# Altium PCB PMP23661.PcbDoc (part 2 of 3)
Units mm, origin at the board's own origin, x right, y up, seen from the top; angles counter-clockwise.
Board outline 209 x 127 mm, 4 copper layers (Top Layer, Layer 1, Layer 2, Bottom Layer), stack 1.787 mm thick; 235 components, 114 nets, 814 pads, 405 vias.
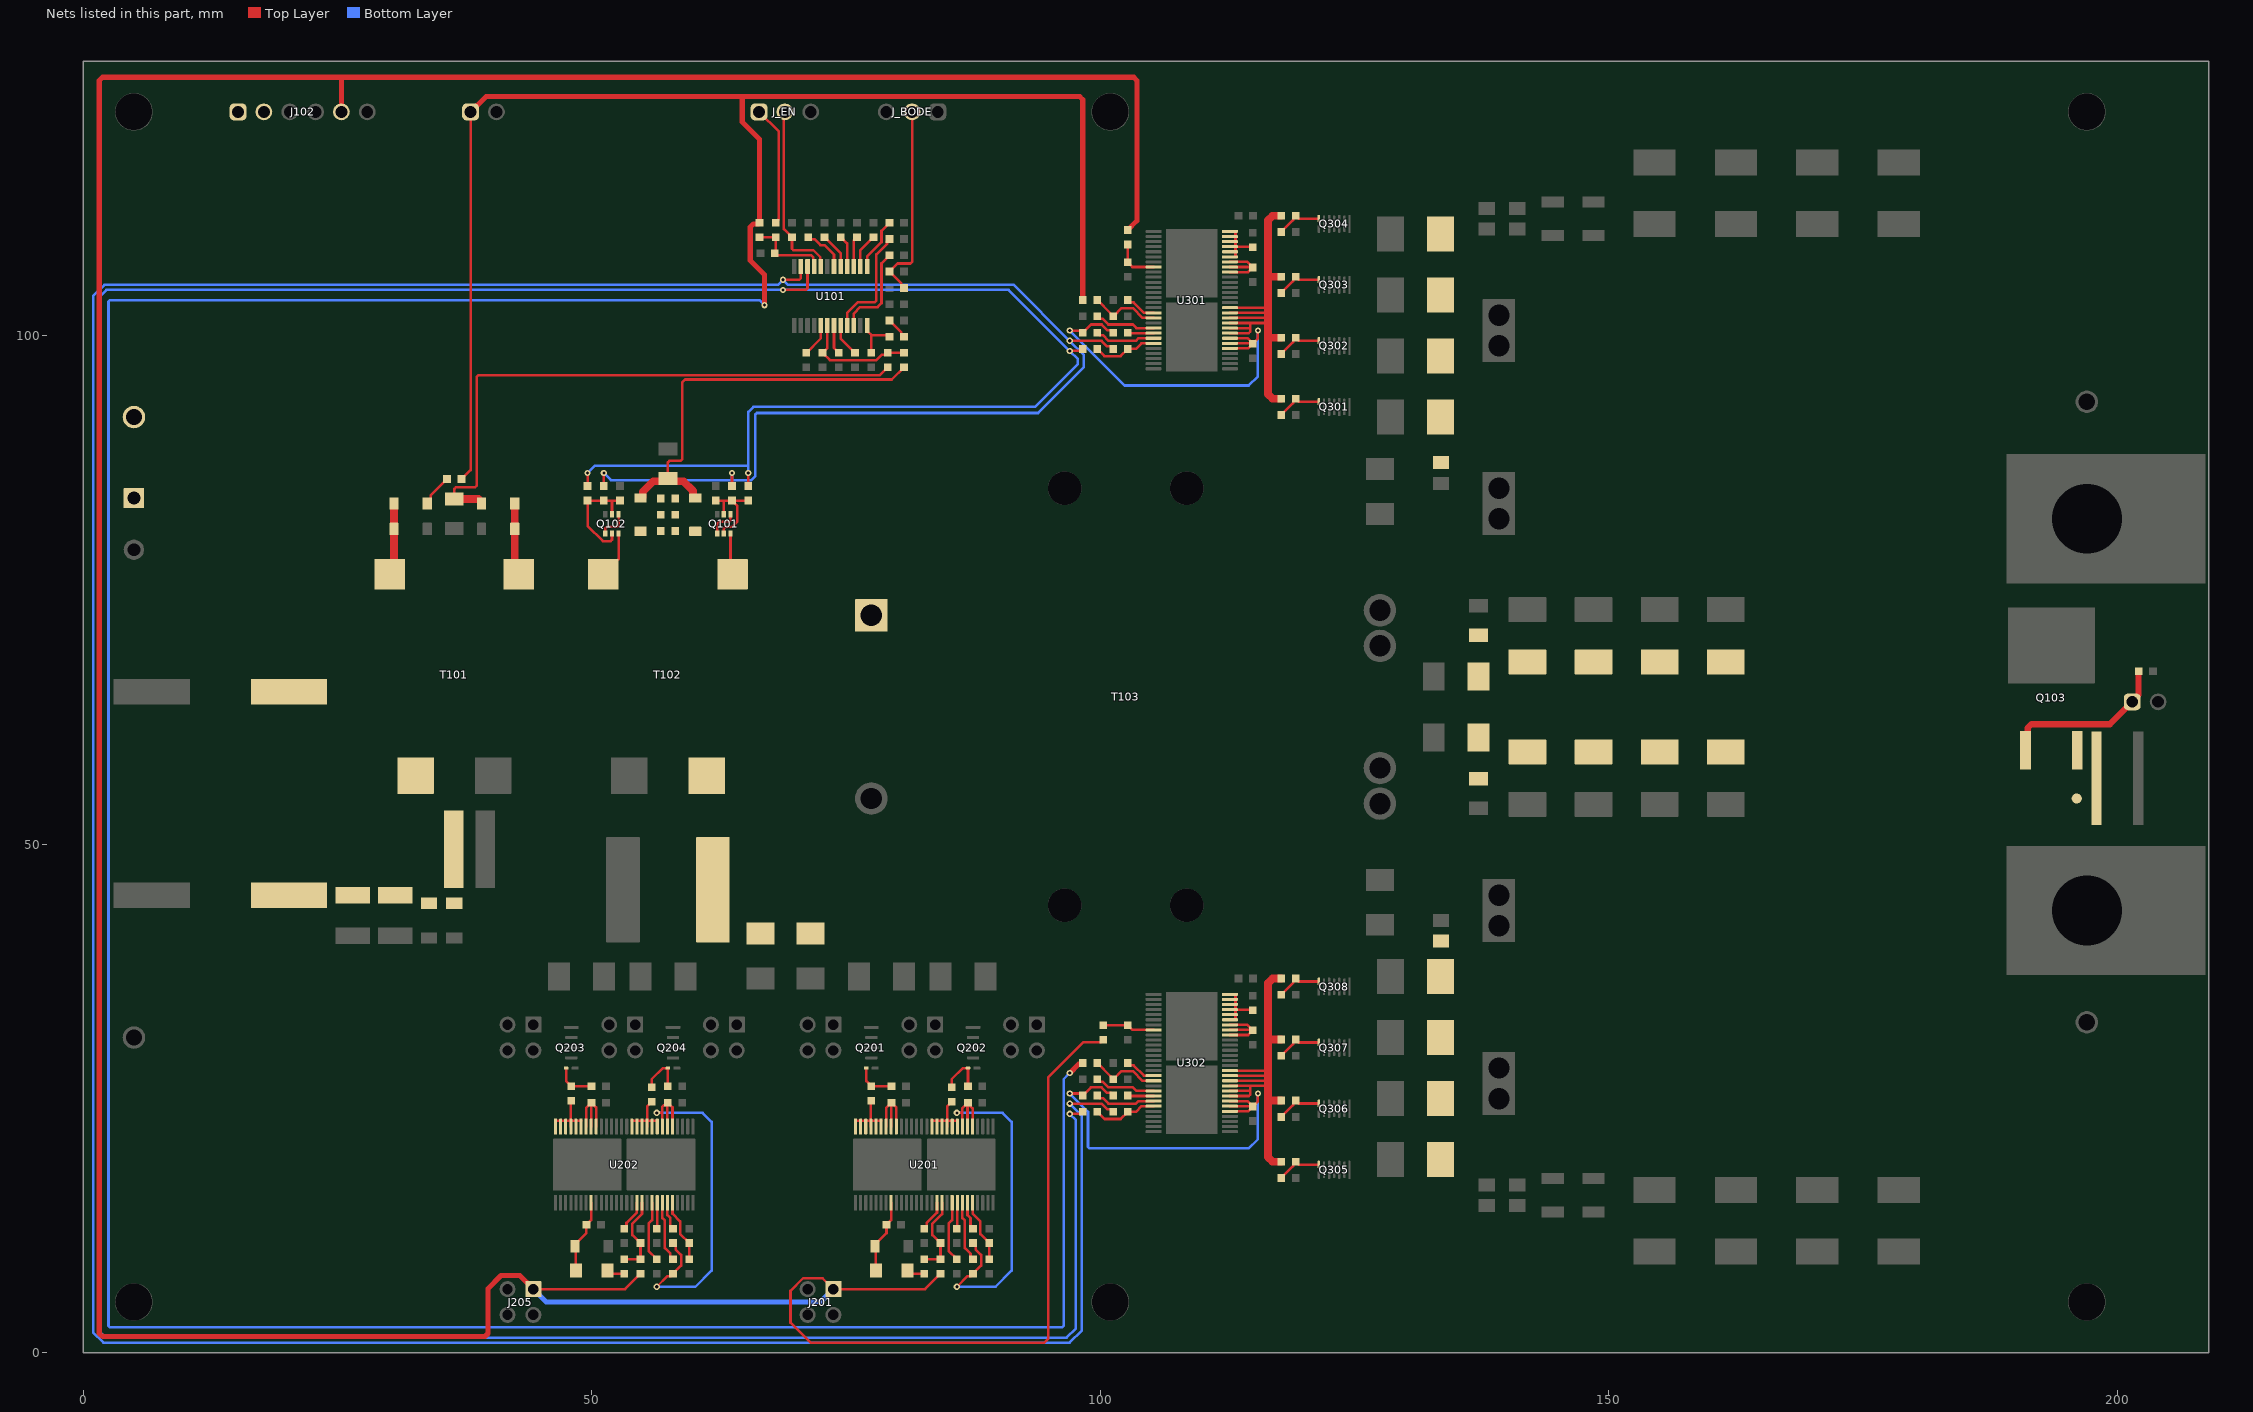
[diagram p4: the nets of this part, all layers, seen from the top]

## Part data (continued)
C109: library part CMP-0007425-5, "CAP, CERM, 5600 pF, 25 V, +/- 10%, X7R, 0603", Cap_Case=0603, Manufacturer=MuRata, Supplier Part Number 1=GRM188R71E562KA01D-ND, TempCo=X7R, Tolerance_%=10%, Value1=Unknown, Value2=25V, ValueDisplayed=5600pF
C110: library part CMP-0084679-1, "CAP, CERM, 0.1 µF, 25 V,+/- 10%, X7R, AEC-Q200 Grade 1, 0603", Cap_Case=0603, Manufacturer=MuRata, TempCo=X7R, Tolerance_%=10%, Value2=25V, ValueDisplayed=0.1µF
C111: library part CMP-0007138-4, "CAP, CERM, 0.47 uF, 16 V, +/- 10%, X7R, AEC-Q200 Grade 1, 0603", Cap_Case=0603, Manufacturer=MuRata, Supplier Part Number 1=490-4775-1-ND, TempCo=X7R, Tolerance_%=10%, Value1=Unknown, Value2=16V, ValueDisplayed=0.47uF
C112: library part CMP-0084283-1, "CAP, CERM, 10 pF, 100 V,+/- 5%, C0G/NP0, AEC-Q200 Grade 1, 0603", Cap_Case=0603, Manufacturer=MuRata, TempCo=C0G/NP0, Tolerance_%=5%, Value2=100V, ValueDisplayed=10pF
C113: library part CMP-0007407-5, "CAP, CERM, 0.012 uF, 25 V, +/- 10%, X7R, 0603", Cap_Case=0603, Manufacturer=MuRata, Supplier Part Number 1=GRM188R71E123KA01D-ND, TempCo=X7R, Tolerance_%=10%, Value1=Unknown, Value2=25V, ValueDisplayed=0.012uF
C114: library part CMP-0007455-4, "CAP, CERM, 470 pF, 50 V, +/- 10%, X7R, 0603", Cap_Case=0603, Manufacturer=MuRata, Supplier Part Number 1=490-1489-1-ND, TempCo=X7R, Tolerance_%=10%, Value1=Unknown, Value2=50V, ValueDisplayed=470pF
C115 C119 C123 C127: library part CMP-0007728-2, "CAP, CERM, 1 uF, 25 V, +/- 10%, X7R, 0805", Cap_Case=0805, Manufacturer=Kemet, Supplier Part Number 1=399-8004-1-ND, TempCo=X7R, Tolerance_%=10%, Value1=Unknown, Value2=25V, ValueDisplayed=1uF
C116 C120 C124 C128: library part CMP-0009078-1, "CAP, CERM, 10 uF, 25 V, +/- 10%, X7R, 1210", Cap_Case=1210, Manufacturer=Kemet, Supplier Part Number 1=399-8224-1-ND, TempCo=X7R, Tolerance_%=10%, Value1=Unknown, Value2=25V, ValueDisplayed=10uF
C117 C118 C121 C122 C125 C126 C129 C130: library part CMP-0012025-2, "CAP, TA, 100 uF, 25 V, +/- 10%, 0.1 ohm, SMD", Cap_Case=E, Manufacturer=Kemet, Supplier Part Number 1=399-5221-1-ND, Tolerance_%=10%, Value1="0.1 ohm", Value2=25V, ValueDisplayed=100uF
C201 C207: library part CMP-0007171-4, "CAP, CERM, 100 pF, 50 V, +/- 5%, C0G/NP0, 0603", Cap_Case=0603, Manufacturer=MuRata, Supplier Part Number 1=490-1427-1-ND, TempCo=C0G/NP0, Tolerance_%=5%, Value1=Unknown, Value2=50V, ValueDisplayed=100pF
C204 C210 C303 C310: library part CMP-0079602-1, "CAP, CERM, 0.1 µF, 50 V,+/- 10%, X7R, AEC-Q200 Grade 1, 0603", Cap_Case=0603, Manufacturer=Kemet, Supplier Part Number 1=399-6856-1-ND, TempCo=X7R, Tolerance_%=10%, Value2=50V, ValueDisplayed=0.1µF
C305 C312: library part CMP-0008881-2, "CAP, CERM, 0.1 uF, 100 V, +/- 10%, X7R, 1206", Cap_Case=1206, Manufacturer=MuRata, Supplier Part Number 1=490-3364-1-ND, TempCo=X7R, Tolerance_%=10%, Value1=Unknown, Value2=100V, ValueDisplayed=0.1uF
C307 C314: library part CMP-0008098-2, "CAP, CERM, 1200 pF, 100 V, +/- 5%, C0G/NP0, 0805", Cap_Case=0805, Manufacturer=MuRata, Supplier Part Number 1=GRM2165C2A122JA01D-ND, TempCo=C0G/NP0, Tolerance_%=5%, Value1=Unknown, Value2=100V, ValueDisplayed=1200pF
D101 D102 D103 D104 D109 D112: library part CMP-0090343-1, "Diode Schottky 100V 250mA (DC) Surface Mount SOD-123", Digikey Part Number=1727-7326-1-ND, Forward Current=250mA, Manufacturer=Nexperia, Max Surge Forward Current=2.5A, Mouser Part Number=841-BAT46GWJ, Operating Temperature Range="to +150°C", Peak Reverse Current=2uA, ValueDisplayed=39pF
D105 D106 D107 D108 D110 D111: library part CMP-0028599-2, "Diode, Schottky, 200 V, 3 A, SMB", Manufacturer="ON Semiconductor", Value1=3A, Value2=0.84V
D113 D114 D301 D302: library part CMP-0028521-2, "Diode, Schottky, 100 V, 1 A, SMB", Manufacturer="ON Semiconductor", Value1=1A, Value2=0.75V
D201 D203: library part CMP-0095320-1, "Diode Schottky 200 V 1A Surface Mount SOD-123W", Digikey Part Number=SS1H20LWRVGCT-ND, Forward Current=1A, Manufacturer="Taiwan Semiconductor", Max Surge Forward Current=30A, Mouser Part Number=821-SS1H20LW, Operating Temperature Range="-55°C to +175°C", Peak Reverse Current=0.1mA
D202 D204: library part CMP-0005752-4, "Diode, Zener, 13 V, 500 mW, SOD-123", Manufacturer="Diodes Inc.", Power_W=500mW, Value1=0.5W
H301 H302 H303 H304 H305 H306: library part CMP-0003652-1, Manufacturer=Keystone, Supplier Part Number 1=36-4820-ND
J101: library part CMP-0074910-1, "Terminal Block, 5.08 mm, 2x1, Brass, TH", Color=Blue, Current_A=15A, Manufacturer="On-Shore Technology", Supplier Part Number 1=ED1609-ND, Voltage_V=300V
J102: library part CMP-0054801-2, "Header, 2.54 mm, 6x1, Gold, TH", Color=Black, Manufacturer="Wurth Elektronik", Supplier Part Number 1=732-5319-ND
J103 J106: library part CMP-0054794-2, "Header, 2.54 mm, 2x1, Gold, TH", Color=Black, Manufacturer="Wurth Elektronik", Supplier Part Number 1=732-5315-ND
J104 J105: library part CMP-0075010-2, "Terminal 70A Lug", Manufacturer=Panduit, Supplier Part Number 1=CXS70-14-C-ND
J201 J202 J203 J204 J205 J206 J207 J208: library part CMP-0127928-1, "Conn Socket Strip SKT 4 POS 2.54mm Solder ST Top Entry Thru-Hole Bulk", Current_A=6.3A, Digikey Part Number=SAM1185-02-ND, Manufacturer=Samtec, Mouser Part Number=200-SSQ10202GD, Operating Temperature Range="-55°C to +125°C", Voltage_V=655V
J_BODE J_EN: library part CMP-0054796-4, "Header, 2.54 mm, 3x1, Gold, TH", Manufacturer="Wurth Elektronik", Supplier Part Number 1=732-5316-ND
L101: library part CMP-0125020-1, "Air Core Inductor, High Current, 117 nH, 44 A, 1212VS Series, ± 20%, 0.00143 ohm, 399 MHz", Manufacturer=Coilcraft, Mouser Part Number=994-1212VS-111MED, Operating Temperature Range=to, Self Resonant Frequency=399MHz, Test Frequency=1MHz, Tolerance_%=20%
L102 L103: library part CMP-0127672-1, "2uH & 48.7Ap INDUCTOR", Manufacturer="Payton Planar", Operating Temperature Range=to
LOGO201: library part CMP-0074835-1, "IEC 61010-1 High Voltage Warning"
Logo301: library part CMP-0074837-2, "IEC 61010-1 Hot Surface Warning", Manufacturer="Texas Instruments"
Logo302: library part CMP-0074836-1, "IEC 61010-1 Caution Warning"
Q101 Q102: library part CMP-0000770-1, "MOSFET, 2-CH, N-CH, 60 V, 0.115 A, SOT-363", Alternate Manufacturer=None, Manufacturer="Fairchild Semiconductor", Supplier Part Number 1=2N7002DWCT-ND
Q103: library part CMP-0097579-1, "MOSFET N-Channel 40 V 194A (Ta) 188W (Ta) Surface Mount DDPAK/TO-263-3", Digikey Part Number=296-51015-1-ND, Drain To Source Breakdown Voltage=40V, Input Capacitace At Vds="4570pF @ 20V", Manufacturer="Texas Instruments", Max Forward Diode Voltage=1V, Mouser Part Number=595-CSD18511KTT, Operating Temperature Range="-55°C to +175°C", Power_W=188W, Pulse Drain Current=400A, Typ Forward Diode Voltage=0.9V
Q201 Q202 Q203 Q204: library part CMP-0033803-1, "MOSFET N-Channel 200 V 32A (Ta) Surface Mount Die", Digikey Part Number=917-1218-1-ND, Drain To Source Breakdown Voltage=200V, Input Capacitace At Vds="1356pF @ 100V", Manufacturer=EPC, Operating Temperature Range="-40°C to +150°C", Pulse Drain Current=162A, Typ Forward Diode Voltage=1.6V
Q301 Q302 Q303 Q304 Q305 Q306 Q307 Q308: library part CMP-0122030-1, "N-Channel 100 V 60A (Ta) Surface Mount Die", Digikey Part Number=917-EPC2088CT-ND, Drain To Source Breakdown Voltage=100V, Input Capacitace At Vds="1864pF @ 50V", Manufacturer=EPC, Operating Temperature Range="-40°C to +150°C", Pulse Drain Current=231A, Typ Forward Diode Voltage=1.5V
R101 R105 R109 R110 R118 R119 R124 R202 R203 R213 R214 R301 R304 R305 R306 R310 R326 R329 R330 R331 R335: library part CMP-0025697-4, "RES, 0, 5%, 0.1 W, AEC-Q200 Grade 0, 0603", Manufacturer=Vishay-Dale, Power_W=100mW, Supplier Part Number 1=541-0.0GCT-ND, TempCo="200 ppm/C", Tolerance_%=5%, Value2=0.1W, Value_Code=0000, ValueDisplayed=0
R102 R103 R107 R114 R115 R116 R205 R206 R216 R217 R303 R328: library part CMP-0022447-4, "RES, 49.9 k, 1%, 0.1 W, AEC-Q200 Grade 0, 0603", Manufacturer=Vishay-Dale, Power_W=100mW, Supplier Part Number 1=541-49.9KHCT-ND, TempCo="100 ppm/C", Tolerance_%=1%, Value2=0.1W, Value_Code=49k9, ValueDisplayed=49.9k
R104 R122: library part CMP-0016768-3, "RES, 1.69, 1%, 0.25 W, AEC-Q200 Grade 0, 1206", Manufacturer=Vishay-Dale, Power_W=250mW, Supplier Part Number 1=541-1.69FFCT-ND, TempCo="100 ppm/C", Tolerance_%=1%, Value2=0.25W, Value_Code=1R69, ValueDisplayed=1.69
R106: library part CMP-0015368-2, "RES, 0, 5%, 2 W, 2512 WIDE", Manufacturer="Vishay Draloric", Power_W=2W, Supplier Part Number 1=RCL0.0ECT-ND, TempCo=ppm/C, Tolerance_%=5%, Value_Code=0000, ValueDisplayed=0
R108: library part CMP-0022052-4, "RES, 147 k, 1%, 0.1 W, AEC-Q200 Grade 0, 0603", Manufacturer=Vishay-Dale, Power_W=100mW, Supplier Part Number 1=541-147KHCT-ND, TempCo="100 ppm/C", Tolerance_%=1%, Value2=0.1W, Value_Code=147k
R111: library part CMP-0022344-4, "RES, 348 k, 1%, 0.1 W, AEC-Q200 Grade 0, 0603", Manufacturer=Vishay-Dale, Power_W=100mW, Supplier Part Number 1=541-348KHCT-ND, TempCo="100 ppm/C", Tolerance_%=1%, Value2=0.1W, Value_Code=348k
R112 R120 R126 R131 R204 R210 R211 R215 R221 R222 R302 R313 R320 R321 R322 R323 R327 R338 R345 R346 R347 R348: library part CMP-0021998-4, "RES, 10.0 k, 1%, 0.1 W, AEC-Q200 Grade 0, 0603", Manufacturer=Vishay-Dale, Power_W=100mW, Supplier Part Number 1=541-10.0KHCT-ND, TempCo="100 ppm/C", Tolerance_%=1%, Value2=0.1W, Value_Code=10k0, ValueDisplayed=10.0k
R113: library part CMP-0022589-4, "RES, 75.0 k, 1%, 0.1 W, AEC-Q200 Grade 0, 0603", Manufacturer=Vishay-Dale, Power_W=100mW, Supplier Part Number 1=541-75.0KHCT-ND, TempCo="100 ppm/C", Tolerance_%=1%, Value2=0.1W, Value_Code=75k0, ValueDisplayed=75.0k
R117: library part CMP-0025736-4, "RES, 1.0 M, 5%, 0.1 W, AEC-Q200 Grade 0, 0603", Manufacturer=Vishay-Dale, Power_W=100mW, Supplier Part Number 1=541-1.0MGCT-ND, TempCo="200 ppm/C", Tolerance_%=5%, Value2=0.1W, Value_Code=1M00, ValueDisplayed=1.0M
R121: library part CMP-0022552-4, "RES, 68.1 k, 1%, 0.1 W, AEC-Q200 Grade 0, 0603", Manufacturer=Vishay-Dale, Power_W=100mW, Supplier Part Number 1=541-68.1KHCT-ND, TempCo="100 ppm/C", Tolerance_%=1%, Value2=0.1W, Value_Code=68k1, ValueDisplayed=68.1k
R123 R125: library part CMP-0022126-4, "RES, 1.50 k, 1%, 0.1 W, AEC-Q200 Grade 0, 0603", Manufacturer=Vishay-Dale, Power_W=100mW, Supplier Part Number 1=541-1.50KHCT-ND, TempCo="100 ppm/C", Tolerance_%=1%, Value2=0.1W, Value_Code=1k50, ValueDisplayed=1.50k
R127: library part CMP-0022003-4, "RES, 10.0, 1%, 0.1 W, AEC-Q200 Grade 0, 0603", Manufacturer=Vishay-Dale, Power_W=100mW, Supplier Part Number 1=541-10.0HCT-ND, TempCo="100 ppm/C", Tolerance_%=1%, Value2=0.1W, Value_Code=10R0, ValueDisplayed=10.0
R128: library part CMP-0022205-4, "RES, 20.5 k, 1%, 0.1 W, AEC-Q200 Grade 0, 0603", Manufacturer=Vishay-Dale, Power_W=100mW, Supplier Part Number 1=541-20.5KHCT-ND, TempCo="100 ppm/C", Tolerance_%=1%, Value2=0.1W, Value_Code=20k5, ValueDisplayed=20.5k
R129: library part CMP-0022113-4, "RES, 1.10 k, 1%, 0.1 W, AEC-Q200 Grade 0, 0603", Manufacturer=Vishay-Dale, Power_W=100mW, Supplier Part Number 1=541-1.10KHCT-ND, TempCo="100 ppm/C", Tolerance_%=1%, Value2=0.1W, Value_Code=1k10, ValueDisplayed=1.10k
R130: library part CMP-0015082-2, "RES, 0.05, 1%, 4 W, 3518 WIDE", Manufacturer=Ohmite, Power_W=4W, Supplier Part Number 1=FCSL90R050FERCT-ND, TempCo="50 ppm/C", Tolerance_%=1%, Value_Code=R050, ValueDisplayed=0.05
R201 R212: library part CMP-0025700-4, "RES, 100, 5%, 0.1 W, AEC-Q200 Grade 0, 0603", Manufacturer=Vishay-Dale, Power_W=100mW, Supplier Part Number 1=541-100GCT-ND, TempCo="200 ppm/C", Tolerance_%=5%, Value2=0.1W, Value_Code=100R, ValueDisplayed=100
R207 R218: library part CMP-0022732-2, "RES, 2.00, 1%, 0.125 W, 0603", Manufacturer=Vishay/Beyschlag, Power_W=125mW, Supplier Part Number 1=MCT06030C2008FP500-ND, TempCo="50 ppm/C", Tolerance_%=1%, Value2=0.125W, Value_Code=2R00, ValueDisplayed=2.00
R208 R209 R219 R220 R312 R315 R316 R317 R318 R337 R340 R341 R342 R343: library part CMP-0022311-4, "RES, 2.49, 1%, 0.1 W, AEC-Q200 Grade 0, 0603", Manufacturer=Vishay-Dale, Power_W=100mW, Supplier Part Number 1=541-2.49HHCT-ND, TempCo="100 ppm/C", Tolerance_%=1%, Value2=0.1W, Value_Code=2R49, ValueDisplayed=2.49
R307 R308 R309 R311 R332 R333 R334 R336: library part CMP-0122385-1, "10 kOhms ±1% 2W Chip Resistor 2512 (6432 Metric) Current Sense Thick Film", Digikey Part Number=118-CRM2512-FX-1002ELFCT-ND, Manufacturer=Bourns, Mouser Part Number=652-CRM2512FX1002ELF, Operating Temperature Range="-55°C to +155°C", Power_W=2W, TempCo=100ppm/°C, Tolerance_%=1%
R314 R319 R324 R325 R339 R344 R349 R350: library part CMP-0096995-1, "Res Thick Film 2512 33 Ohm 1% 3W ±100ppm/C Pad SMD Automotive T/R", Digikey Part Number=A121219CT-ND, Manufacturer="TE Connectivity", Mouser Part Number=279-3522330KFT, Operating Temperature Range="-55°C to +155°C", Power_W=3W, TempCo=100ppm/°C, Tolerance_%=1%
T101 T102: library part CMP-0122471-1, "Current Transformer 1:50", Manufacturer="Payton Planar", Operating Temperature Range=to
T103: library part CMP-0127699-1, "TITLE 1000W SMPS TRANSFORMER", Manufacturer="Payton Planar", Operating Temperature Range=to
TP101 TP104: library part CMP-0055147-2, "Test Point, Multipurpose, Red, TH", Color=Red, Manufacturer="Keystone Electronics", Supplier Part Number 1=36-5010-ND
TP102 TP105: library part CMP-0055148-2, "Test Point, Multipurpose, Black, TH", Color=Black, Manufacturer="Keystone Electronics", Supplier Part Number 1=36-5011-ND
TP103: library part CMP-0003825-1, "1mm Test Point, SMT", Manufacturer=Any
U101: library part CMP-0092938-1, Manufacturer="Texas Instruments", Operating Temperature Range=to
U201 U202 U301 U302: library part CMP-0120202-4, Manufacturer="Texas Instruments", Operating Temperature Range=to

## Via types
v1: diameter 0.61, hole 0.305, Top Layer to Bottom Layer, 289 vias
v2: diameter 0.813, hole 0.406, Top Layer to Bottom Layer, 116 vias

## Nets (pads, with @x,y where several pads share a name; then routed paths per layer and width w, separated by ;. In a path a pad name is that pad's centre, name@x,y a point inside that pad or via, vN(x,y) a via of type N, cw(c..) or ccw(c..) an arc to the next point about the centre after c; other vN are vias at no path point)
+12Vp: J102.5 J201.1 J205.1 R202.1 R213.1 R310.1 R335.1 | length 421.5
  Top Layer w0.254: J205.1@44.27,6.27 53.281,6.27 R213.1@54.8,7.789 ; R202.1@84.3,7.789 82.781,6.27 ; R335.1@100.3,30.789 100.057,30.546 98.346,30.546 94.9,27.1 94.9,1.4 94.5,1 71.525,1 69.554,2.972 69.554,6.099 70.789,7.334 72.706,7.334 J201.1@73.77,6.27 ; J201.1@73.77,6.27 82.781,6.27 ; J201.1@73.77,6.27 82.781,6.27
  Top Layer w0.508: J102.5@25.4,122 25.4,125.4 ; J205.1@44.27,6.27 42.94,7.6 41.1,7.6 39.8,6.3 39.8,1.898 39.502,1.6 1.898,1.6 1.6,1.898 1.6,125.102 1.898,125.4 25.4,125.4 ; R310.1@102.7,110.394 103.6,111.294 103.6,125.102 103.302,125.4 25.4,125.4
  Bottom Layer w0.508: J205.1@44.27,6.27 45.54,5 72.5,5 J201.1@73.77,6.27
+12Vs: J103.1 R101.2 R105.1 R306.1 R331.1 | length 425.8
  Top Layer w0.254: R105.1@37.211,85.9 38.1,86.789 J103.1@38.1,122
  Top Layer w0.508: J103.1@38.1,122 39.6,123.5 64.8,123.5 ; v1(67,103) 67,106 65.6,107.4 65.6,110.687 65.898,110.984 66.373,110.984 R101.2@66.5,111.111 66.5,119.307 64.8,121.007 64.8,123.5 ; v1@97.019,27.519 97.873,28.373 98.162,28.373 R331.1@98.289,28.5 ; R306.1@98.289,103.5 98.289,123.202 97.991,123.5 64.8,123.5
  Bottom Layer w0.254: v1(67,103) 66.5,103.5 2.649,103.5 2.5,103.351 2.5,2.649 2.649,2.5 96.251,2.5 96.4,2.649 96.4,26.9 v1(97,27.5)
HV: C101.1 C102.1 C103.1 C105.1 C107.1 C108.1 J101.1 J102.1 J102.2 R106.2 T101.1 TP101.1
NetC104_1: C104.1 R101.1 R102.1 U101.9 | length 8.2
  Top Layer w0.254: R101.1@66.5,109.689 R102.1@68.1,109.689 C104.1@68.1,108.3 ; C104.1@68.211,108.3 C104.1@68.011,108.1 68.211,107.9 71.6,107.9 71.799,107.701 71.799,106.876 U101.9@71.875,106.8
NetC106_2: C106.2 U101.17 | length 3.3
  Top Layer w0.254: C106.2@71.1,98.311 72.525,99.736 U101.17@72.525,101
NetC109_2: C109.2 U101.5 | length 3.5
  Top Layer w0.254: C109.2@72.9,109.689 74.475,108.114 U101.5@74.475,106.8
NetC110_1: C110.1 U101.22 | length 9.4
  Top Layer w0.254: U101.22@75.775,101 75.775,102.175 76.4,102.8 78.1,102.8 78.5,103.2 78.5,107.111 C110.1@79.289,107.9
NetC111_2: C111.2 U101.20 | length 3.3
  Top Layer w0.254: U101.20@74.475,101 74.475,99.736 C111.2@75.9,98.311
NetC112_1: C112.1 R123.1 R125.1 U101.18 | length 11.5
  Top Layer w0.254: U101.18@73.175,101 73.175,98.786 C112.1@72.7,98.311 73.411,97.6 78,97.6 78.509,98.109 78.898,98.109 R123.1@79.1,98.311 R125.1@80.7,98.311
NetC113_1: C113.1 R126.1 | length 2.2
  Top Layer w0.254: C113.1@79.289,101.5 80.457,100.332 80.457,100.154 R126.1@80.711,99.9
NetC114_1: C114.1 R126.2 U101.24 | length 4.7
  Top Layer w0.254: U101.24@77.075,101 77.075,100.475 77.5,100.05 ; C114.1@77.5,98.311 77.5,100.05 ; R126.2@79.289,99.9 79.139,100.05 77.5,100.05
NetC201_1: C201.1 R201.1 U201.24 | length 12.4
  Top Layer w0.254: 87.45,13.69 88.208,12.932 ; 87.45,13.69 U201.24@87.45,14.75 87.45,13.69 ; 87.45,13.69 88.208,12.932 ; 88.208,11.681 88.208,12.932 ; 88.208,11.681 C201.1@89.1,10.789 ; 88.208,11.681 C201.1@89.1,10.789 ; 88.208,11.681 88.208,12.932 ; C201.1@89.1,10.789 R201.1@89.1,9.211 C201.1@89.1,10.789
NetC202_1: C202.1 R202.2 R207.1 U201.18 | length 15.7
  Top Layer w0.254: 83.5,11.589 C202.1@84.3,10.789 ; 83.5,11.589 83.5,12.7 ; 83.5,11.589 83.5,12.7 ; 83.5,11.589 C202.1@84.3,10.789 ; 83.5,12.7 84.45,13.65 ; 83.5,12.7 84.45,13.65 ; R202.2@84.3,9.211 C202.1@84.3,10.789 ; R202.2@84.3,9.211 R207.1@82.7,9.211 R202.2@84.3,9.211 ; R202.2@84.3,9.211 C202.1@84.3,10.789 ; 84.45,13.65 U201.18@84.45,14.75 84.45,13.65
NetC203_2: C203.2 U201.17 | length 6.1
  Top Layer w0.254: C203.2@82.931,12.442 82.931,12.773 ; C203.2@82.931,12.442 C203.2@82.7,12.211 C203.2@82.931,12.442 ; C203.2@82.931,12.442 82.931,12.773 ; 82.931,12.773 83.95,13.792 ; 82.931,12.773 83.95,13.792 ; 83.95,13.792 U201.17@83.95,14.75 83.95,13.792
NetC204_2: C204.2 D201.1 D202.1 U201.8 | length 14.5
  Top Layer w0.254: D202.1@77.95,10.74 78.989,11.779 ; D202.1@77.95,10.74 D201.1@77.95,8.1 D202.1@77.95,10.74 ; D202.1@77.95,10.74 78.989,11.779 ; 78.989,11.779 C204.2@78.989,12.6 ; 78.989,11.779 C204.2@78.989,12.6 ; C204.2@78.989,12.6 79.45,13.061 ; C204.2@78.989,12.6 79.45,13.061 ; 79.45,13.061 U201.8@79.45,14.75 79.45,13.061
NetC205_2: C205.2 U201.48 U201.49 U201.50 | length 7.2
  Top Layer w0.254: U201.50@78.95,22.25 78.95,24.061 C205.2@79.489,24.6 ; U201.49@79.45,22.25 79.45,24.346 79.543,24.439 79.65,24.439 79.95,24.139 U201.48@79.95,22.25
NetC206_2: C206.2 R203.1 R204.2 U201.33 U201.34 U201.35 | length 40.1
  Top Layer w0.254: v1(85.9,6.5) 86.948,7.548 87.259,7.548 88.3,8.589 88.3,9.636 87.754,10.182 87.754,10.535 R203.1@87.5,10.789 ; v1(85.9,23.6) 86.45,23.6 ; U201.35@86.45,22.25 86.45,23.6 ; U201.34@86.95,22.25 86.95,24.461 86.989,24.5 87.45,24.039 U201.33@87.45,22.25 ; C206.2@86.989,24.6 86.45,24.061 86.45,23.6
  Bottom Layer w0.254: v1(85.9,6.5) 89.7,6.5 91.3,8.1 91.3,22.7 90.4,23.6 v1(85.9,23.6)
NetC207_2: C207.2 R212.1 U202.24 | length 6.2
  Top Layer w0.254: U202.24@57.95,14.75 57.95,13.69 58.708,12.932 58.708,11.681 C207.2@59.6,10.789 R212.1@59.6,9.211
NetC208_1: C208.1 R213.2 R218.1 U202.18 | length 7.9
  Top Layer w0.254: R218.1@53.2,9.211 R213.2@54.8,9.211 C208.1@54.8,10.789 54,11.589 54,12.7 54.95,13.65 U202.18@54.95,14.75
NetC209_2: C209.2 U202.17 | length 3.1
  Top Layer w0.254: C209.2@53.2,12.211 53.431,12.442 53.431,12.773 54.45,13.792 U202.17@54.45,14.75
NetC210_2: C210.2 D203.1 D204.1 U202.8 | length 7.3
  Top Layer w0.254: D203.1@48.45,8.1 48.45,10.74 49.489,11.779 C210.2@49.489,12.6 49.95,13.061 U202.8@49.95,14.75
NetC211_2: C211.2 U202.48 U202.49 U202.50 | length 7.2
  Top Layer w0.254: U202.50@49.45,22.25 49.45,24.061 C211.2@49.989,24.6 ; U202.49@49.95,22.25 49.95,24.346 50.043,24.439 50.15,24.439 50.45,24.139 U202.48@50.45,22.25
NetC212_2: C212.2 R214.1 R215.2 U202.33 U202.34 U202.35 | length 40.2
  Top Layer w0.254: v1(56.4,6.5) 57.448,7.548 57.759,7.548 58.8,8.589 58.8,9.636 58.254,10.182 58.254,10.535 R214.1@58,10.789 ; v1(56.4,23.6) 56.95,23.6 ; U202.35@56.95,22.25 56.95,23.6 ; U202.34@57.45,22.25 57.45,24.461 C212.2@57.489,24.5 ; U202.33@57.95,22.25 57.95,24.139 C212.2@57.489,24.6 57.4,24.511 57.235,24.346 57.099,24.346 56.95,24.197 56.95,23.6
  Bottom Layer w0.254: v1(56.4,6.5) 60.2,6.5 61.8,8.1 61.8,22.7 60.9,23.6 v1(56.4,23.6)
NetC301_1: C301.1 R306.2 U301.18 | length 13.9
  Top Layer w0.254: C301.1@101.035,102.154 C301.1@101.035,102.176 ; C301.1@101.035,102.154 C301.1@101.289,101.9 ; C301.1@101.035,102.154 C301.1@101.289,101.9 ; C301.1@101.035,102.154 C301.1@101.035,102.176 ; C301.1@101.035,102.176 R306.2@99.711,103.5 C301.1@101.035,102.176 ; C301.1@101.289,101.9 102.089,102.7 ; C301.1@101.289,101.9 102.089,102.7 ; 102.089,102.7 103.2,102.7 ; 102.089,102.7 103.2,102.7 ; 103.2,102.7 104.15,101.75 ; 103.2,102.7 104.15,101.75 ; 104.15,101.75 U301.18@105.25,101.75 104.15,101.75
NetC302_2: C302.2 U301.17 | length 6.1
  Top Layer w0.254: C302.2@102.942,103.269 103.273,103.269 ; C302.2@102.942,103.269 C302.2@102.711,103.5 C302.2@102.942,103.269 ; C302.2@102.942,103.269 103.273,103.269 ; 103.273,103.269 104.292,102.25 ; 103.273,103.269 104.292,102.25 ; 104.292,102.25 U301.17@105.25,102.25 104.292,102.25
NetC303_2: C303.2 R310.2 U301.8 | length 4.3
  Top Layer w0.254: R310.2@102.7,108.789 C303.2@102.7,107.211 103.161,106.75 U301.8@105.25,106.75
NetC304_2: C304.2 U301.48 U301.49 U301.50 | length 7.2
  Top Layer w0.254: U301.48@112.75,106.25 114.539,106.25 C304.2@115,106.711 ; U301.49@112.75,106.75 114.961,106.75 C304.2@115,106.711 ; U301.50@112.75,107.25 114.461,107.25 C304.2@115,106.711
NetC305_1: C305.1 D301.1 R307.1 R308.1 R309.1 R311.1
NetC306_2: C306.2 R302.2 R305.1 U301.33 U301.34 U301.35 | length 39.3
  Top Layer w0.254: v1(97,100.5) 98.089,100.5 R302.2@98.289,100.3 99.089,101.1 100.136,101.1 100.682,100.554 101.035,100.554 R305.1@101.289,100.3 ; U301.33@112.75,98.75 114.539,98.75 C306.2@115,99.211 ; U301.34@112.75,99.25 114.961,99.25 C306.2@115,99.211 ; U301.35@112.75,99.75 114.461,99.75 C306.2@115,99.211 ; v1(115.5,100.5) 115.5,99.711 C306.2@115,99.211
  Bottom Layer w0.254: v1(97,100.5) 102.4,95.1 114.6,95.1 115.5,96 v1(115.5,100.5)
NetC307_2: C307.2 R314.2 R319.2 R324.2 R325.2
NetC308_1: C308.1 R331.2 U302.18 | length 6.9
  Top Layer w0.254: R331.2@99.711,28.5 101.035,27.176 101.035,27.154 C308.1@101.289,26.9 102.089,27.7 103.2,27.7 104.15,26.75 U302.18@105.25,26.75
NetC309_2: C309.2 U302.17 | length 3.1
  Top Layer w0.254: C309.2@102.711,28.5 102.942,28.269 103.273,28.269 104.292,27.25 U302.17@105.25,27.25
NetC310_2: C310.2 R335.2 U302.8 | length 5.1
  Top Layer w0.254: R335.2@100.3,32.211 C310.2@102.7,32.211 103.161,31.75 U302.8@105.25,31.75
NetC311_2: C311.2 U302.48 U302.49 U302.50 | length 7.2
  Top Layer w0.254: U302.48@112.75,31.25 114.539,31.25 C311.2@115,31.711 ; U302.49@112.75,31.75 114.961,31.75 C311.2@115,31.711 ; U302.50@112.75,32.25 114.461,32.25 C311.2@115,31.711
NetC312_1: C312.1 D302.1 R332.1 R333.1 R334.1 R336.1
NetC313_2: C313.2 R327.2 R330.1 U302.33 U302.34 U302.35 | length 41.3
  Top Layer w0.254: v1(97,25.5) 98.089,25.5 R327.2@98.289,25.3 99.089,26.1 100.136,26.1 100.682,25.554 101.035,25.554 R330.1@101.289,25.3 ; U302.33@112.75,23.75 114.539,23.75 C313.2@115,24.211 ; U302.34@112.75,24.25 114.961,24.25 C313.2@115,24.211 ; U302.35@112.75,24.75 114.461,24.75 C313.2@115,24.211 ; v1(115.5,25.5) 115.5,24.711 C313.2@115,24.211
  Bottom Layer w0.254: v1(97,25.5) 98.8,23.7 98.8,20.249 98.949,20.1 114.6,20.1 115.5,21 v1(115.5,25.5)
NetC314_2: C314.2 R339.2 R344.2 R349.2 R350.2
NetD101_1: D101.1 R104.2 R123.2 | length 57.8
  Top Layer w0.254: R104.2@36.5,83.95 36.5,84.951 36.649,85.1 38.551,85.1 38.7,85.249 38.7,95.951 38.849,96.1 78.311,96.1 R123.2@79.1,96.889
  Top Layer w0.762: R104.2@36.5,83.95 38.87,83.95 39.165,83.655 D101.1@39.165,83.5
NetD101_2: D101.2 D102.1 T101.3 | length 7.1
  Top Layer w0.762: D101.2@42.435,83.5 42.435,76.965 T101.3@42.85,76.55
NetD103_1: D103.1 R105.2 | length 3.2
  Top Layer w0.254: D103.1@33.835,83.5 34.163,83.828 34.163,84.274 R105.2@35.789,85.9
NetD103_2: D103.2 D104.1 T101.4 | length 7.1
  Top Layer w0.762: T101.4@30.15,76.55 30.565,76.965 D103.2@30.565,83.5
NetD109_1: D109.1 D112.1 R122.2 R125.2 | length 40.8
  Top Layer w0.254: R122.2@57.5,85.95 57.5,87.551 57.649,87.7 58.751,87.7 58.9,87.849 58.9,95.4 59.194,95.694 79.505,95.694 R125.2@80.7,96.889
  Top Layer w0.762: D112.1@54.8,84.035 54.955,84.035 55.029,84.109 55.029,84.663 56.047,85.681 57.231,85.681 R122.2@57.5,85.95 57.769,85.681 59.019,85.681 59.971,84.729 59.971,84.109 60.045,84.035 D109.1@60.2,84.035
NetD109_2: D109.2 Q101.6 R114.1 R115.1 R116.1 T102.3 | length 4.1
  Top Layer w0.254: Q101.6@63.65,80.55 63.65,76.75 T102.3@63.85,76.55
NetD110_2: D110.2 D111.1 L101.2 T102.2 T103.1
NetD112_2: D112.2 Q102.6 R114.2 R115.2 R116.2 T102.4 | length 4.6
  Top Layer w0.254: T102.4@51.15,76.55 52.65,78.05 Q102.6@52.65,80.55
NetD201_2: D201.2 R207.2 | length 3.6
  Top Layer w0.254: D201.2@81.361,7.789 D201.2@81.05,8.1 D201.2@81.361,7.789 ; D201.2@81.361,7.789 R207.2@82.7,7.789 D201.2@81.361,7.789
NetD203_2: D203.2 R218.2 | length 1.8
  Top Layer w0.254: D203.2@51.55,8.1 51.861,7.789 R218.2@53.2,7.789
NetJ106_1: J106.1 Q103.1 R131.2 | length 16.9
  Top Layer w0.6: Q103.1@190.96,59.245 191.185,59.47 191.185,61.449 191.536,61.8 199.26,61.8 J106.1@201.46,64 201.46,64.061 202.089,64.69 R131.2@202.089,67
NetJ_BODE_2: J_BODE.2 R127.1 R128.2 | length 19.5
  Top Layer w0.254: R128.2@80.711,104.7 80.457,104.954 80.457,105.132 R127.1@79.289,106.3 80.089,107.1 81.34,107.1 81.5,107.26 J_BODE.2@81.5,122
NetJ_EN_1: J_EN.1 R102.2 | length 11.8
  Top Layer w0.254: J_EN.1@66.46,122 68.4,120.06 68.4,111.514 68.354,111.468 68.354,111.365 R102.2@68.1,111.111
NetJ_EN_2: J_EN.2 R103.1 U101.8 | length 17.9
  Top Layer w0.254: J_EN.2@69,122 68.9,121.9 68.9,110.489 R103.1@69.7,109.689 69.7,108.549 69.849,108.4 71.8,108.4 72.474,107.726 72.474,106.851 U101.8@72.525,106.8
NetQ101_1: Q101.1 Q101.4 | length 3
  Top Layer w0.254: Q101.4@62.35,80.55 62.35,81.554 62.499,81.703 63.501,81.703 63.65,81.852 Q101.1@63.65,82.45
NetQ101_2: Q101.2 Q101.5 R109.1 R110.1 R112.2 | length 8.9
  Top Layer w0.254: R112.2@62.2,83.789 63,83.789 ; Q101.5@63,80.55 63,81.051 63.149,81.2 63.797,81.2 64.3,81.703 64.3,83.289 R110.1@63.8,83.789 ; Q101.2@63,82.45 63,83.789 ; R109.1@65.4,83.789 63,83.789
NetQ102_1: Q102.1 Q102.4 | length 3
  Top Layer w0.254: Q102.4@51.35,80.45 51.35,81.051 51.499,81.2 52.501,81.2 52.65,81.349 Q102.1@52.65,82.35
NetQ102_2: Q102.2 Q102.5 R118.1 R119.1 R120.2 | length 10.7
  Top Layer w0.254: Q102.5@52,80.55 52,79.949 51.851,79.8 51.1,79.8 49.6,81.3 R119.1@49.6,83.789 R118.1@51.2,83.789 52,83.789 ; Q102.2@52,82.45 52,83.789 ; R120.2@52.8,83.789 52,83.789
NetQ103_3: Q103.3 R130.2 TP103.1
NetQ201_1: Q201.1 R208.1 R210.1 | length 4
  Top Layer w0.254: Q201.1@77,28 77,26.711 R208.1@77.5,26.211 77.511,26.2 R210.1@79.489,26.2
NetQ202_1: Q202.1 R209.1 R211.1 | length 4.6
  Top Layer w0.254: R209.1@85.4,26.111 85.4,26.9 86.5,28 Q202.1@87,28 R211.1@87,26.211
NetQ203_1: Q203.1 R219.1 R221.1 | length 4
  Top Layer w0.254: Q203.1@47.5,28 47.5,26.711 R219.1@48,26.211 48.011,26.2 R221.1@49.989,26.2
NetQ204_1: Q204.1 R220.1 R222.1 | length 4.6
  Top Layer w0.254: R220.1@55.9,26.111 55.9,26.9 57,28 Q204.1@57.5,28 R222.1@57.5,26.211
NetQ301_1: Q301.1 R315.1 R320.1 | length 4.6
  Top Layer w0.254: R320.1@117.789,92.2 118.957,93.368 118.957,93.546 R315.1@119.211,93.8 119.499,93.512 Q301.1@121.5,93.512
NetQ302_1: Q302.1 R316.1 R321.1 | length 4.6
  Top Layer w0.254: R321.1@117.789,98.2 118.957,99.368 118.957,99.546 R316.1@119.211,99.8 119.499,99.512 Q302.1@121.5,99.512
NetQ303_1: Q303.1 R317.1 R322.1 | length 4.6
  Top Layer w0.254: R322.1@117.789,104.2 118.957,105.368 118.957,105.546 R317.1@119.211,105.8 119.499,105.512 Q303.1@121.5,105.512
NetQ304_1: Q304.1 R318.1 R323.1 | length 4.6
  Top Layer w0.254: R323.1@117.789,110.2 118.957,111.368 118.957,111.546 R318.1@119.211,111.8 119.499,111.512 Q304.1@121.5,111.512
NetQ305_1: Q305.1 R340.1 R345.1 | length 4.6
  Top Layer w0.254: R345.1@117.789,17.2 118.957,18.368 118.957,18.546 R340.1@119.211,18.8 119.499,18.512 Q305.1@121.5,18.512
NetQ306_1: Q306.1 R341.1 R346.1 | length 4.6
  Top Layer w0.254: R346.1@117.789,23.2 118.957,24.368 118.957,24.546 R341.1@119.211,24.8 119.499,24.512 Q306.1@121.5,24.512
NetQ307_1: Q307.1 R342.1 R347.1 | length 4.6
  Top Layer w0.254: R347.1@117.789,29.2 118.957,30.368 118.957,30.546 R342.1@119.211,30.8 119.499,30.512 Q307.1@121.5,30.512
NetQ308_1: Q308.1 R343.1 R348.1 | length 4.6
  Top Layer w0.254: R348.1@117.789,35.2 118.957,36.368 118.957,36.546 R343.1@119.211,36.8 119.499,36.512 Q308.1@121.5,36.512
NetR107_1: R107.1 U101.4 | length 3.1
  Top Layer w0.254: R107.1@74.5,109.689 75.125,109.064 U101.4@75.125,106.8
NetR108_2: R108.2 U101.2 | length 3.4
  Top Layer w0.254: U101.2@76.425,106.8 76.425,108.414 R108.2@77.7,109.689
NetR111_2: R111.2 U101.1 | length 5.2
  Top Layer w0.254: U101.1@77.075,106.8 77.076,106.801 77.076,107.776 78.5,109.2 78.5,110.311 R111.2@79.289,111.1
NetR113_2: R113.2 U101.3 | length 3
  Top Layer w0.254: U101.3@75.775,106.8 75.775,109.364 R113.2@76.1,109.689
NetR117_2: R117.2 U101.6 | length 4.4
  Top Layer w0.254: R117.2@71.3,109.689 71.491,109.498 71.902,109.498 72.5,108.9 72.9,108.9 73.825,107.975 U101.6@73.825,106.8
NetR121_2: R121.2 U101.21 | length 11.2
  Top Layer w0.254: U101.21@75.125,101 75.125,102.225 76.2,103.3 77.851,103.3 78,103.449 78,108 79.035,109.035 79.035,109.246 R121.2@79.289,109.5
NetR124_1: R124.1 U101.19 | length 2.9
  Top Layer w0.254: U101.19@73.825,101 73.825,98.786 R124.1@74.3,98.311
NetR203_2: R203.2 U201.23 | length 5.5
  Top Layer w0.254: 86.95,13.548 87.246,13.252 ; 86.95,13.548 U201.23@86.95,14.75 86.95,13.548 ; 86.95,13.548 87.246,13.252 ; R203.2@87.246,12.465 87.246,13.252 ; R203.2@87.246,12.465 R203.2@87.5,12.211 R203.2@87.246,12.465 ; R203.2@87.246,12.465 87.246,13.252
NetR204_1: R204.1 U201.22 | length 11.9
  Top Layer w0.254: 86.45,13.261 U201.22@86.45,14.75 86.45,13.261 ; 86.45,13.261 86.7,13.011 ; 86.45,13.261 86.7,13.011 ; 86.7,10.3 87.248,9.752 ; 86.7,10.3 86.7,13.011 ; 86.7,10.3 87.248,9.752 ; 86.7,10.3 86.7,13.011 ; R204.1@87.248,9.463 87.248,9.752 ; R204.1@87.248,9.463 R204.1@87.5,9.211 R204.1@87.248,9.463 ; R204.1@87.248,9.463 87.248,9.752
NetR205_1: R205.1 U201.20 | length 12
  Top Layer w0.254: 85.1,10.011 85.1,12.7 ; 85.1,10.011 R205.1@85.9,9.211 85.1,10.011 ; 85.1,10.011 85.1,12.7 ; 85.1,12.7 85.45,13.05 ; 85.1,12.7 85.45,13.05 ; 85.45,13.05 U201.20@85.45,14.75 85.45,13.05
NetR206_1: R206.1 U201.21 | length 5.1
  Top Layer w0.254: R206.1@85.95,12.261 U201.21@85.95,14.75 R206.1@85.95,12.261 ; R206.1@85.95,12.261 R206.1@85.9,12.211 R206.1@85.95,12.261
NetR208_2: R208.2 U201.51 U201.52 U201.53 U201.54 U201.55 U201.56 | length 5.1
  Top Layer w0.254: U201.56@75.95,22.8 76.45,22.8 76.95,22.8 77.5,22.8 77.95,22.8 U201.51@78.45,22.8 ; U201.53@77.45,22.25 77.45,24.739 R208.2@77.5,24.789
NetR209_2: R209.2 U201.36 U201.37 U201.38 U201.39 U201.40 U201.41 | length 5.1
  Top Layer w0.254: U201.41@83.45,22.8 U201.36@85.95,22.8 ; U201.38@84.95,22.25 84.95,24.239 R209.2@85.4,24.689
NetR214_2: R214.2 U202.23 | length 2.8
  Top Layer w0.254: U202.23@57.45,14.75 57.45,13.548 57.746,13.252 57.746,12.465 R214.2@58,12.211
NetR215_1: R215.1 U202.22 | length 6
  Top Layer w0.254: U202.22@56.95,14.75 56.95,13.261 57.2,13.011 57.2,10.3 57.748,9.752 57.748,9.463 R215.1@58,9.211
NetR216_1: R216.1 U202.20 | length 6
  Top Layer w0.254: U202.20@55.95,14.75 55.95,13.05 55.6,12.7 55.6,10.011 R216.1@56.4,9.211
NetR217_1: R217.1 U202.21 | length 2.6
  Top Layer w0.254: R217.1@56.4,12.211 56.45,12.261 U202.21@56.45,14.75
NetR219_2: R219.2 U202.51 U202.52 U202.53 U202.54 U202.55 U202.56 | length 5.1
  Top Layer w0.254: U202.56@46.45,22.8 46.95,22.8 47.45,22.8 48,22.8 48.45,22.8 U202.51@48.95,22.8 ; U202.53@47.95,22.25 47.95,24.739 R219.2@48,24.789
NetR220_2: R220.2 U202.36 U202.37 U202.38 U202.39 U202.40 U202.41 | length 5.1
  Top Layer w0.254: U202.41@53.95,22.8 U202.36@56.45,22.8 ; U202.38@55.45,22.25 55.45,24.239 R220.2@55.9,24.689
NetR301_2: R301.2 R304.2 U301.23 | length 6.4
  Top Layer w0.254: R304.2@99.711,98.7 100.419,97.992 102.003,97.992 R301.2@102.711,98.7 103.498,98.7 104.048,99.25 U301.23@105.25,99.25
NetR302_1: R302.1 U301.22 | length 6
  Top Layer w0.254: R302.1@99.711,100.3 99.963,100.048 100.252,100.048 100.8,99.5 103.504,99.5 103.754,99.75 U301.22@105.25,99.75
NetR303_1: R303.1 U301.20 | length 12
  Top Layer w0.254: R303.1@99.963,101.648 100.252,101.648 ; R303.1@99.963,101.648 R303.1@99.711,101.9 R303.1@99.963,101.648 ; R303.1@99.963,101.648 100.252,101.648 ; 100.252,101.648 100.8,101.1 ; 100.252,101.648 100.8,101.1 ; 100.8,101.1 103.2,101.1 ; 100.8,101.1 103.2,101.1 ; 103.2,101.1 103.55,100.75 ; 103.2,101.1 103.55,100.75 ; 103.55,100.75 U301.20@105.25,100.75 103.55,100.75
NetR305_2: R305.2 U301.21 | length 5.1
  Top Layer w0.254: R305.2@102.761,100.25 U301.21@105.25,100.25 R305.2@102.761,100.25 ; R305.2@102.761,100.25 R305.2@102.711,100.3 R305.2@102.761,100.25
NetR312_2: R312.2 U301.51 U301.52 U301.53 U301.54 U301.55 U301.56 | length 4.8
  Top Layer w0.254: U301.53@112.75,108.75 114.939,108.75 R312.2@115,108.689 ; U301.51@113.3,107.75 U301.56@113.3,110.25
NetR315_2: R315.2 R316.2 R317.2 R318.2 U301.36 U301.37 U301.38 U301.39 U301.40 U301.41 | length 42.7
  Top Layer w0.254: U301.36@112.75,100.25 114.601,100.25 114.75,100.399 114.75,100.799 ; U301.37@112.75,100.75 114.701,100.75 114.75,100.799 ; U301.38@112.75,101.25 114.7,101.25 ; U301.39@112.75,101.75 116.5,101.75 ; U301.40@112.75,102.25 116.5,102.25 ; U301.41@112.75,102.75 116.481,102.75 116.5,102.731 ; 116.5,101.3 116.45,101.25 114.7,101.25 ; 114.7,101.25 114.75,101.2 114.75,100.799
  Top Layer w0.762: R315.2@117.789,93.8 116.946,93.8 116.5,94.246 116.5,99.711 ; R316.2@117.789,99.8 116.589,99.8 116.5,99.711 ; R317.2@117.789,105.8 116.55,105.8 116.5,105.75 ; R318.2@117.789,111.8 116.946,111.8 116.5,111.354 116.5,105.75 ; 116.5,99.711 116.5,101.3 116.5,101.75 116.5,102.25 116.5,102.731 116.5,105.75
NetR326_2: R326.2 R329.2 U302.23 | length 6.4
  Top Layer w0.254: R329.2@99.711,23.7 100.419,22.992 102.003,22.992 R326.2@102.711,23.7 103.498,23.7 104.048,24.25 U302.23@105.25,24.25
NetR327_1: R327.1 U302.22 | length 6
  Top Layer w0.254: R327.1@99.711,25.3 99.963,25.048 100.252,25.048 100.8,24.5 103.511,24.5 103.761,24.75 U302.22@105.25,24.75
NetR328_1: R328.1 U302.20 | length 6
  Top Layer w0.254: R328.1@99.711,26.9 99.963,26.648 100.252,26.648 100.8,26.1 103.2,26.1 103.55,25.75 U302.20@105.25,25.75
NetR330_2: R330.2 U302.21 | length 2.6
  Top Layer w0.254: R330.2@102.711,25.3 102.761,25.25 U302.21@105.25,25.25
NetR337_2: R337.2 U302.51 U302.52 U302.53 U302.54 U302.55 U302.56 | length 4.8
  Top Layer w0.254: U302.53@112.75,33.75 114.939,33.75 R337.2@115,33.689 ; U302.51@113.3,32.75 U302.56@113.3,35.25
NetR340_2: R340.2 R341.2 R342.2 R343.2 U302.36 U302.37 U302.38 U302.39 U302.40 U302.41 | length 42.7
  Top Layer w0.254: U302.36@112.75,25.25 114.601,25.25 114.75,25.399 114.75,25.799 ; U302.37@112.75,25.75 114.701,25.75 114.75,25.799 ; U302.38@112.75,26.25 114.7,26.25 ; U302.39@112.75,26.75 116.5,26.75 ; U302.40@112.75,27.25 116.5,27.25 ; U302.41@112.75,27.75 116.481,27.75 116.5,27.731 ; 116.5,26.3 116.45,26.25 114.7,26.25 ; 114.7,26.25 114.75,26.2 114.75,25.799
  Top Layer w0.762: R340.2@117.789,18.8 116.946,18.8 116.5,19.246 116.5,24.711 ; R341.2@117.789,24.8 116.589,24.8 116.5,24.711 ; R342.2@117.789,30.8 116.55,30.8 116.5,30.75 ; R343.2@117.789,36.8 116.946,36.8 116.5,36.354 116.5,30.75 ; 116.5,24.711 116.5,26.3 116.5,26.75 116.5,27.25 116.5,27.731 116.5,30.75
OUTA: R109.2 R119.2 R304.1 R329.1 U101.10 | length 386
  Top Layer w0.254: R119.2@49.6,85.211 v1(49.6,86.5) ; R109.2@65.4,85.211 v1(65.4,86.5) ; v1(68.8,104.5) 71.075,104.5 71.224,104.649 U101.10@71.225,106.8 U101.10@71.225,106.8 ; v1(97,23.5) 98.089,23.5 R329.1@98.289,23.7 ; v1(97,98.5) 98.089,98.5 R304.1@98.289,98.7
  Bottom Layer w0.254: v1(49.6,86.5) 50.3,87.2 65.4,87.2 ; v1(65.4,86.5) 65.4,87.2 ; v1(97,23.5) 97.6,22.9 97.6,2.4 96.7,1.5 2.2,1.5 1.5,2.2 1.5,103.7 2.3,104.5 v1(68.8,104.5) 91,104.5 v1(97,98.5) 97.8,97.7 97.8,97.2 93.6,93 65.9,93 65.4,92.5 65.4,87.2
OUTB: R110.2 R118.2 R301.1 R326.1 U101.11 | length 396.3
  Top Layer w0.254: R118.2@51.2,85.211 v1(51.2,86.5) ; R110.2@63.8,85.211 v1(63.8,86.5) ; v1(68.8,105.5) 70.426,105.5 70.575,105.649 U101.11@70.575,106.8 ; v1(97,24.5) 100.136,24.5 100.682,23.954 101.035,23.954 R326.1@101.289,23.7 ; v1(97,99.5) 100.136,99.5 100.682,98.954 101.035,98.954 R301.1@101.289,98.7
  Bottom Layer w0.254: v1(51.2,86.5) 51.9,85.8 63.8,85.8 ; v1(63.8,86.5) 63.8,85.8 ; v1(97,24.5) 98.2,23.3 98.2,2.2 97,1 2,1 1,2 1,103.9 2.1,105 68.3,105 v1(68.8,105.5) 69.3,105 91.5,105 v1(97,99.5) 98.4,98.1 98.4,96.905 93.895,92.4 66.249,92.4 66.1,92.251 66.1,86.2 65.7,85.8 63.8,85.8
